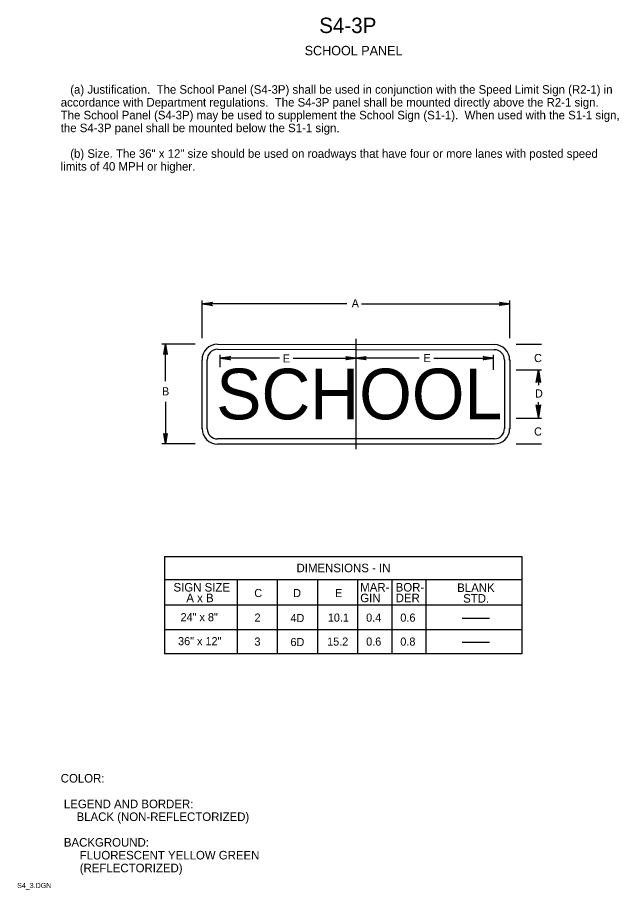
# Model space of a CAD drawing. Extents: x 0.013 to 0.188, y 0.004 to 0.259.
import ezdxf

# ---------------------------------------------------------------- set-up
doc = ezdxf.new("R2010")
doc.units = 0
for name, color, linetype in [('1', 7, 'Continuous'), ('2', 7, 'Continuous'), ('3', 7, 'Continuous')]:
    doc.layers.add(name, color=color, linetype=linetype)

# ---------------------------------------------------------------- blocks, each defined once
blk = doc.blocks.new('RARROW')
at = {"layer": '3'}
for p, q in [((-2.156, 0.285), (-2.2665, 0.384625)), ((-2.2665, 0.384625), (0, 0)), ((0, 0), (-2.2665, -0.379125)), ((-2.156, 0.285), (-2.075625, 0.12075)), ((0, 0), (-2.156, 0.285)), ((-2.14975, -0.2705), (0, 0)), ((-2.075625, 0.12075), (0, 0)), ((0, 0), (-2.074, -0.108)), ((-2.2665, -0.379125), (-2.14975, -0.2705)), ((-2.074, -0.108), (-2.14975, -0.2705))]:
    blk.add_line(p, q, dxfattribs=at)

msp = doc.modelspace()

# ---------------------------------------------------------------- linework, layer by layer
at = {"layer": '1'}
msp.add_line((0.11163, 0.165), (0.11163, 0.13275), dxfattribs=at)
at = {"layer": '3'}
for p, q in [((0.06663, 0.16525), (0.06663, 0.17625)), ((0.15663, 0.16525), (0.15663, 0.17625)), ((0.109, 0.17525), (0.06663, 0.17525)), ((0.11325, 0.17525), (0.15663, 0.17525)), ((0.06459, 0.1635), (0.05488, 0.1635)), ((0.05588, 0.15263), (0.05588, 0.1635)), ((0.07113, 0.1635), (0.15213, 0.16337)), ((0.1585, 0.1635), (0.16587, 0.1635)), ((0.07113, 0.162), (0.15213, 0.16187)), ((0.11163, 0.16225), (0.11163, 0.16037)), ((0.06663, 0.13875), (0.06663, 0.15888)), ((0.06813, 0.13875), (0.06813, 0.15888)), ((0.07188, 0.15675), (0.07188, 0.16037)), ((0.08925, 0.15938), (0.07188, 0.15938)), ((0.09325, 0.15938), (0.11163, 0.15938)), ((0.13012, 0.15938), (0.11163, 0.15938)), ((0.13437, 0.15938), (0.15188, 0.15938)), ((0.15188, 0.156), (0.15188, 0.16037)), ((0.15513, 0.15888), (0.15513, 0.13875)), ((0.15663, 0.15888), (0.15663, 0.13875)), ((0.1585, 0.156), (0.16587, 0.156)), ((0.165, 0.156), (0.165, 0.1515)), ((0.05588, 0.14663), (0.05588, 0.13437)), ((0.165, 0.142), (0.165, 0.1465)), ((0.1585, 0.14188), (0.16587, 0.14188)), ((0.15213, 0.13575), (0.07113, 0.13575)), ((0.06459, 0.13437), (0.05488, 0.13437)), ((0.15213, 0.13425), (0.07113, 0.13425)), ((0.1585, 0.13437), (0.16587, 0.13437)), ((0.05563, 0.10138), (0.16012, 0.10138)), ((0.05563, 0.10138), (0.05563, 0.07286)), ((0.16012, 0.10138), (0.16012, 0.07286)), ((0.16012, 0.0945), (0.05563, 0.0945)), ((0.07687, 0.0945), (0.07687, 0.07286)), ((0.07687, 0.0945), (0.07687, 0.07286)), ((0.08862, 0.0945), (0.08862, 0.07286)), ((0.10038, 0.0945), (0.10038, 0.07286)), ((0.11213, 0.0945), (0.11213, 0.07286)), ((0.12212, 0.0945), (0.12212, 0.07286)), ((0.13212, 0.0945), (0.13212, 0.07286)), ((0.16012, 0.08713), (0.05563, 0.08713)), ((0.14275, 0.08338), (0.15075, 0.08338)), ((0.16012, 0.07988), (0.05563, 0.07988)), ((0.14275, 0.07636), (0.15075, 0.07636)), ((0.16012, 0.07286), (0.05563, 0.07286))]:
    msp.add_line(p, q, dxfattribs=at)
for centre, radius, start, end in [((0.07119, 0.15891), 0.00459, 90.7913, 180.7913), ((0.1521, 0.15885), 0.0045, 0, 90), ((0.07119, 0.15891), 0.00309, 91.1755, 181.1755), ((0.1521, 0.15885), 0.003, 0, 90), ((0.07113, 0.13878), 0.00453, 179.9414, 269.9414), ((0.07109, 0.13875), 0.00297, 180.0894, 270.0894), ((0.1521, 0.13879), 0.0045, 270, 0), ((0.1521, 0.13879), 0.003, 270, 0)]:
    msp.add_arc(centre, radius, start, end, dxfattribs=at)

# ---------------------------------------------------------------- block references
for p, xscale, yscale, rotation in [((0.06663, 0.17525), 0.0013236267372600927, 0.001309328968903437, 180), ((0.05588, 0.1635), 0.0013236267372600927, 0.001309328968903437, 90), ((0.07188, 0.15938), 0.0013236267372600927, 0.001309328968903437, 180), ((0.11163, 0.15938), 0.0013236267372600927, 0.001309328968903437, 180), ((0.165, 0.156), 0.0016545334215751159, 0.0016366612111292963, 90), ((0.165, 0.142), 0.0016545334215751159, 0.0016366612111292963, -90), ((0.05588, 0.13437), 0.0013236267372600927, 0.001309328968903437, -90)]:
    msp.add_blockref('RARROW', p, dxfattribs=dict(at, xscale=xscale, yscale=yscale, rotation=rotation))
at = {"layer": '3', "xscale": 0.0013236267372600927, "yscale": 0.001309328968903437}
for p in [(0.15663, 0.17525), (0.11163, 0.15938), (0.15188, 0.15938)]:
    msp.add_blockref('RARROW', p, dxfattribs=at)

# ---------------------------------------------------------------- texts
at = {"layer": '1'}
for s, height, p in [('S4-3P', 0.0045, (0.10088, 0.2545)), ('SCHOOL PANEL', 0.0027503, (0.09663, 0.248)), ('COLOR:', 0.0025, (0.02525, 0.03525)), (' LEGEND AND BORDER:', 0.0024998, (0.02525, 0.02775)), ('     BLACK (NON-REFLECTORIZED)', 0.0024998, (0.02525, 0.024)), (' BACKGROUND:', 0.0024998, (0.02525, 0.0165)), ('      FLUORESCENT YELLOW GREEN ', 0.0024998, (0.02525, 0.01275)), ('      (REFLECTORIZED)', 0.0024998, (0.02525, 0.009)), ('S4_3.DGN', 0.0015, (0.0125, 0.00438))]:
    msp.add_text(s, height=height, dxfattribs=at).set_placement(p)
at = {"layer": '2'}
for s, height, p in [('   (a) Justification.  The School Panel (S4-3P) shall be used in conjunction with the Speed Limit Sign (R2-1) in ', 0.00249975, (0.02525, 0.23675)), ('accordance with Department regulations.  The S4-3P panel shall be mounted directly above the R2-1 sign.', 0.00249975, (0.02525, 0.233)), ('The School Panel (S4-3P) may be used to supplement the School Sign (S1-1).  When used with the S1-1 sign,', 0.00249975, (0.02525, 0.22925)), ('the S4-3P panel shall be mounted below the S1-1 sign.', 0.0024998, (0.02525, 0.2255)), ('   (b) Size. The 36" x 12" size should be used on roadways that have four or more lanes with posted speed ', 0.00249975, (0.02525, 0.218)), ('limits of 40 MPH or higher.', 0.0024998, (0.02525, 0.21425))]:
    msp.add_text(s, height=height, dxfattribs=at).set_placement(p)
at = {"layer": '3'}
for s, height, p in [('A', 0.00238, (0.11038, 0.17425)), ('E', 0.00238, (0.09025, 0.15813)), ('E', 0.00238, (0.13137, 0.15825)), ('C', 0.00238, (0.16375, 0.15825)), ('SCHOOL', 0.014813, (0.07075, 0.1415)), ('B', 0.00238, (0.05488, 0.1485)), ('D', 0.00238, (0.164, 0.14788)), ('C', 0.00238, (0.16375, 0.13675)), ('DIMENSIONS - IN', 0.0024998, (0.09424, 0.09677)), ('SIGN SIZE', 0.0025, (0.05825, 0.09112)), ('C', 0.00238, (0.08188, 0.0895)), ('D', 0.00238, (0.09325, 0.0895)), ('E', 0.00238, (0.1055, 0.0895)), ('MAR-', 0.0025, (0.11288, 0.09112)), ('BOR-', 0.0025, (0.12325, 0.09112)), ('BLANK', 0.0025, (0.14125, 0.091)), ('A x B', 0.0025, (0.062, 0.088)), ('GIN', 0.0025, (0.11288, 0.088)), ('DER', 0.0025, (0.12325, 0.088)), ('STD.', 0.0025, (0.143, 0.08788)), ('24" x 8"', 0.002375, (0.06031, 0.08244)), ('2', 0.00238, (0.08195, 0.08231)), ('4D', 0.002375, (0.09247, 0.08219)), ('10.1', 0.002375, (0.1034, 0.08231)), ('0.4', 0.002375, (0.11461, 0.08231)), ('0.6', 0.002375, (0.12462, 0.08231)), ('36" x 12"', 0.002375, (0.05959, 0.07542)), ('3', 0.00238, (0.08193, 0.0753)), ('6D', 0.002375, (0.09247, 0.07517)), ('15.2', 0.002375, (0.1032, 0.0753)), ('0.6', 0.002375, (0.11462, 0.0753)), ('0.8', 0.002375, (0.12461, 0.0753))]:
    msp.add_text(s, height=height, dxfattribs=at).set_placement(p)

doc.saveas('drawing.dxf')
